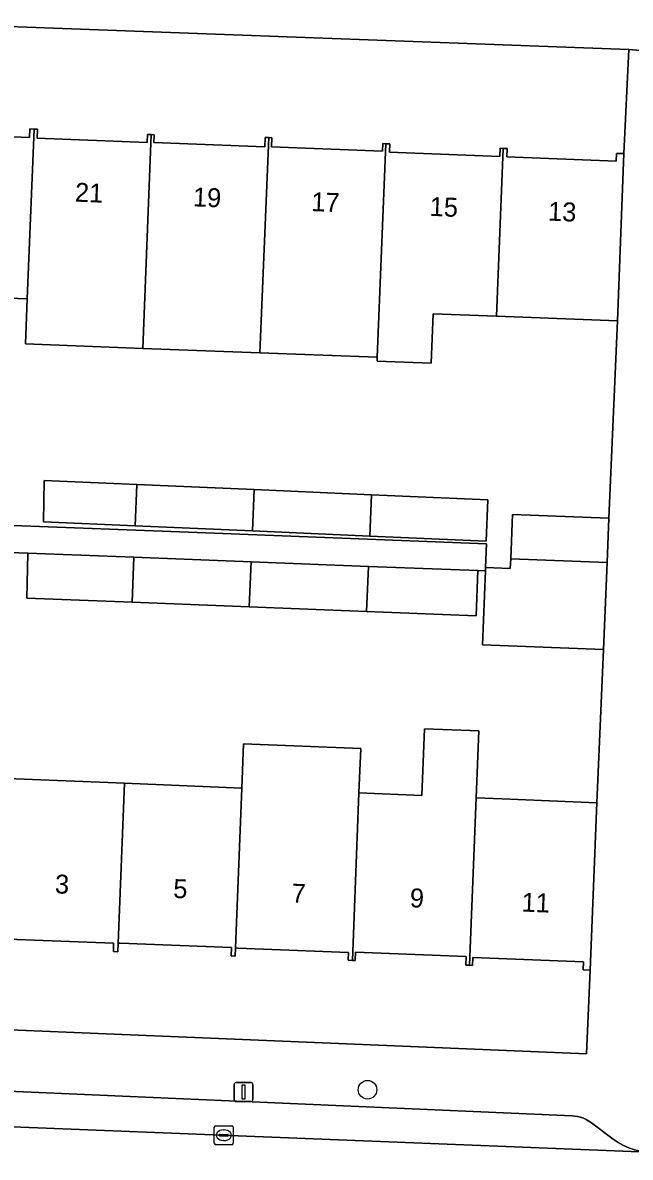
# Model space of a CAD drawing. Extents: x 161354 to 162026, y 386504 to 387460.
# Drawn here: x 161814.8 to 161846.8, y 386692 to 386751.9 of the extents above; entities that cross this region are included whole.
import ezdxf

# ---------------------------------------------------------------- set-up
doc = ezdxf.new("R2010")
doc.units = 0
for name, color, linetype in [('IMGEO_Boom', 7, 'Continuous'), ('IMGEO_Erf', 7, 'Continuous'), ('IMGEO_Kolk', 7, 'Continuous'), ('IMGEO_Lichtmast', 7, 'Continuous'), ('IMGEO_Muur', 7, 'Continuous'), ('IMGEO_Pand', 7, 'Continuous'), ('IMGEO_Pand_nummerreeks', 7, 'Continuous'), ('IMGEO_Parkeervlak_open', 7, 'Continuous'), ('IMGEO_Rijbaan_lokaal_open', 7, 'Continuous'), ('IMGEO_Voetpad_gesloten', 7, 'Continuous'), ('IMGEO_Voetpad_open', 7, 'Continuous')]:
    doc.layers.add(name, color=color, linetype=linetype)

msp = doc.modelspace()

# ---------------------------------------------------------------- linework, layer by layer
at = {"layer": 'IMGEO_Boom'}
msp.add_circle((161832.96, 386695.526), 0.489, dxfattribs=at)
at = {"layer": 'IMGEO_Erf'}
for points in [[(161809.293, 386746.023), (161815.126, 386745.793), (161815.144, 386746.245), (161815.365, 386746.236), (161815.544, 386746.229), (161815.525, 386745.761), (161821.329, 386745.532), (161821.346, 386745.956), (161821.552, 386745.948), (161821.705, 386745.942), (161821.689, 386745.529), (161827.535, 386745.298), (161827.555, 386745.795), (161827.744, 386745.787), (161827.919, 386745.78), (161827.9, 386745.297), (161833.748, 386745.067), (161833.764, 386745.473), (161833.929, 386745.466), (161834.13, 386745.458), (161834.112, 386745.015), (161839.945, 386744.785), (161839.962, 386745.225), (161840.117, 386745.219), (161840.331, 386745.21), (161840.314, 386744.776), (161846.077, 386744.549), (161846.094, 386744.958), (161846.478, 386744.946), (161846.74, 386750.435), (161809.266, 386751.829)], [(161814.265, 386725.315), (161823.973, 386724.938), (161839.242, 386724.345), (161839.186, 386723.088), (161840.493, 386723.035), (161840.513, 386723.552), (161840.606, 386725.894), (161845.692, 386725.694), (161846.151, 386736.123), (161841.155, 386736.308), (161839.762, 386736.36), (161836.431, 386736.483), (161836.322, 386733.886), (161833.463, 386733.992), (161833.472, 386734.206), (161827.282, 386734.435), (161821.099, 386734.664), (161814.906, 386734.894), (161815.005, 386737.277), (161808.728, 386737.51)], [(161813.957, 386711.965), (161820.14, 386711.709), (161826.323, 386711.453), (161826.421, 386713.789), (161832.609, 386713.533), (161832.506, 386711.197), (161835.832, 386711.059), (161835.97, 386714.581), (161838.826, 386714.469), (161838.688, 386710.94), (161840.072, 386710.883), (161845.067, 386710.676), (161845.419, 386718.76), (161839.025, 386719.013), (161839.179, 386722.914), (161838.778, 386722.93), (161838.686, 386720.551), (161832.908, 386720.776), (161826.723, 386721.017), (161820.537, 386721.258), (161814.983, 386721.474), (161815.032, 386723.854), (161813.139, 386723.923)], [(161844.701, 386701.843), (161844.343, 386701.857), (161844.359, 386702.284), (161838.517, 386702.509), (161838.501, 386702.091), (161838.342, 386702.097), (161838.15, 386702.105), (161838.168, 386702.565), (161832.327, 386702.791), (161832.31, 386702.343), (161832.16, 386702.349), (161831.934, 386702.358), (161831.95, 386702.779), (161826.123, 386703.004), (161825.994, 386703.009), (161825.977, 386702.586), (161825.766, 386702.594), (161825.783, 386703.041), (161819.911, 386703.267), (161819.81, 386703.271), (161819.792, 386702.808), (161819.548, 386702.817), (161819.565, 386703.268), (161814.006, 386703.483)], [(161798.896, 386699.324), (161844.507, 386697.427), (161844.701, 386701.843)]]:
    msp.add_lwpolyline(points, dxfattribs=at)
msp.add_lwpolyline([(161826.982, 386727.208), (161833.167, 386726.938), (161839.315, 386726.669), (161839.22, 386724.486), (161833.075, 386724.754), (161826.891, 386725.024), (161820.705, 386725.294), (161815.857, 386725.506), (161815.906, 386727.691), (161820.796, 386727.478)], close=True, dxfattribs=at)
at = {"layer": 'IMGEO_Kolk'}
for p, q in [((161824.95, 386693.625), (161825.802, 386693.625)), ((161824.875, 386692.699), (161824.875, 386693.551)), ((161825.134, 386693.119), (161825.134, 386693.131)), ((161825.572, 386693.082), (161825.174, 386693.082)), ((161825.177, 386693.168), (161825.575, 386693.168)), ((161825.363, 386693.405), (161825.388, 386693.405)), ((161825.618, 386693.131), (161825.618, 386693.119)), ((161825.876, 386693.551), (161825.876, 386692.699)), ((161825.802, 386692.625), (161824.95, 386692.625)), ((161825.386, 386692.845), (161825.361, 386692.845))]:
    msp.add_line(p, q, dxfattribs=at)
for points in [[(161824.95, 386693.625), (161825.802, 386693.625)], [(161824.875, 386692.699), (161824.875, 386693.551)], [(161825.876, 386693.551), (161825.876, 386692.699)], [(161825.802, 386692.625), (161824.95, 386692.625)]]:
    msp.add_lwpolyline(points, dxfattribs=at)
for centre, radius, start, end in [((161824.952, 386693.549), 0.0765, 91.55205, 178.44795), ((161824.952, 386693.549), 0.0765, 91.55205, 178.44795), ((161825.8, 386693.549), 0.0765, 1.55205, 88.44795), ((161825.8, 386693.549), 0.0765, 1.55205, 88.44795), ((161825.174, 386693.128), 0.0403, 85.87752, 175.75265), ((161825.171, 386693.118), 0.0366, 178.93798, 274.71019), ((161825.575, 386693.125), 0.043, 264.86636, 352.45326), ((161825.579, 386693.13), 0.0386, 1.73085, 96.63898), ((161824.952, 386692.701), 0.0765, 181.55205, 268.44795), ((161824.952, 386692.701), 0.0765, 181.55205, 268.44795), ((161825.8, 386692.701), 0.0765, 271.55205, 358.44795), ((161825.8, 386692.701), 0.0765, 271.55205, 358.44795)]:
    msp.add_arc(centre, radius, start, end, dxfattribs=at)
for centre, major_axis, ratio, start_param, end_param in [((161825.362, 386693.125), (-0.387, 0.002), 0.722429, 4.712389, 7.853982), ((161825.387, 386693.125), (-0.39, 0.002), 0.717154, 1.570796, 4.712389)]:
    msp.add_ellipse(centre, major_axis=major_axis, ratio=ratio, start_param=start_param, end_param=end_param, dxfattribs=at)
at = {"layer": 'IMGEO_Lichtmast'}
for p, q in [((161825.923, 386695.006), (161825.923, 386695.806)), ((161825.923, 386695.806), (161825.923, 386695.006)), ((161826.023, 386695.906), (161826.813, 386695.906)), ((161826.813, 386695.906), (161826.023, 386695.906)), ((161826.913, 386695.806), (161826.913, 386695.006)), ((161826.913, 386695.006), (161826.913, 386695.806)), ((161826.813, 386694.906), (161826.023, 386694.906)), ((161826.023, 386694.906), (161826.813, 386694.906))]:
    msp.add_line(p, q, dxfattribs=at)
msp.add_lwpolyline([(161826.343, 386695.781), (161826.493, 386695.781), (161826.493, 386695.031), (161826.343, 386695.031), (161826.343, 386695.781)], dxfattribs=at)
for centre, start, end in [((161826.023, 386695.806), 90, 180), ((161826.023, 386695.806), 90, 180), ((161826.813, 386695.806), 0, 90), ((161826.813, 386695.806), 360, 90), ((161826.023, 386695.006), 180, 270), ((161826.023, 386695.006), 180, 270), ((161826.813, 386695.006), 270, 0), ((161826.813, 386695.006), 270, 0)]:
    msp.add_arc(centre, 0.1, start, end, dxfattribs=at)
at = {"layer": 'IMGEO_Muur'}
msp.add_lwpolyline([(161845.419, 386718.76), (161845.067, 386710.676)], dxfattribs=at)
at = {"layer": 'IMGEO_Pand'}
for points in [[(161808.827, 386740.749), (161808.735, 386737.728), (161808.728, 386737.51), (161815.005, 386737.277), (161815.365, 386746.236), (161815.144, 386746.245), (161815.126, 386745.793), (161809.293, 386746.023), (161809.311, 386746.486), (161808.997, 386746.481)], [(161821.552, 386745.948), (161821.346, 386745.956), (161821.329, 386745.532), (161815.525, 386745.761), (161815.544, 386746.229), (161815.365, 386746.236), (161815.005, 386737.277), (161814.906, 386734.894), (161821.099, 386734.664)], [(161827.282, 386734.435), (161827.744, 386745.787), (161827.555, 386745.795), (161827.535, 386745.298), (161821.689, 386745.529), (161821.705, 386745.942), (161821.552, 386745.948), (161821.099, 386734.664)], [(161833.472, 386734.206), (161833.929, 386745.466), (161833.764, 386745.473), (161833.748, 386745.067), (161827.9, 386745.297), (161827.919, 386745.78), (161827.744, 386745.787), (161827.282, 386734.435)], [(161833.463, 386733.992), (161836.322, 386733.886), (161836.431, 386736.483), (161839.762, 386736.36), (161840.117, 386745.219), (161839.962, 386745.225), (161839.945, 386744.785), (161834.112, 386745.015), (161834.13, 386745.458), (161833.929, 386745.466), (161833.472, 386734.206)], [(161846.478, 386744.946), (161846.094, 386744.958), (161846.077, 386744.549), (161840.314, 386744.776), (161840.331, 386745.21), (161840.117, 386745.219), (161839.762, 386736.36), (161841.155, 386736.308), (161846.151, 386736.123)], [(161815.906, 386727.691), (161815.857, 386725.506), (161820.705, 386725.294), (161820.796, 386727.478)], [(161820.796, 386727.478), (161820.705, 386725.294), (161826.891, 386725.024), (161826.982, 386727.208)], [(161826.982, 386727.208), (161826.891, 386725.024), (161833.075, 386724.754), (161833.167, 386726.938)], [(161839.22, 386724.486), (161839.315, 386726.669), (161833.167, 386726.938), (161833.075, 386724.754)], [(161845.692, 386725.694), (161840.606, 386725.894), (161840.513, 386723.552), (161845.6, 386723.354)], [(161815.032, 386723.854), (161814.983, 386721.474), (161820.537, 386721.258), (161820.636, 386723.636)], [(161820.636, 386723.636), (161820.537, 386721.258), (161826.723, 386721.017), (161826.823, 386723.395)], [(161845.6, 386723.354), (161840.513, 386723.552), (161840.493, 386723.035), (161839.186, 386723.088), (161839.179, 386722.914), (161839.025, 386719.013), (161845.419, 386718.76)], [(161826.823, 386723.395), (161826.723, 386721.017), (161832.908, 386720.776), (161833.008, 386723.154)], [(161838.686, 386720.551), (161838.778, 386722.93), (161833.008, 386723.154), (161832.908, 386720.776)], [(161838.688, 386710.94), (161838.826, 386714.469), (161835.97, 386714.581), (161835.832, 386711.059), (161832.506, 386711.197), (161832.16, 386702.349), (161832.31, 386702.343), (161832.327, 386702.791), (161838.168, 386702.565), (161838.15, 386702.105), (161838.342, 386702.097)], [(161832.506, 386711.197), (161832.609, 386713.533), (161826.421, 386713.789), (161826.323, 386711.453), (161825.994, 386703.009), (161826.123, 386703.004), (161831.95, 386702.779), (161831.934, 386702.358), (161832.16, 386702.349)], [(161820.14, 386711.709), (161813.957, 386711.965), (161813.626, 386703.497), (161814.006, 386703.483), (161819.565, 386703.268), (161819.548, 386702.817), (161819.792, 386702.808), (161819.81, 386703.271)], [(161826.323, 386711.453), (161820.14, 386711.709), (161819.81, 386703.271), (161819.911, 386703.267), (161825.783, 386703.041), (161825.766, 386702.594), (161825.977, 386702.586), (161825.994, 386703.009)], [(161845.067, 386710.676), (161840.072, 386710.883), (161838.688, 386710.94), (161838.342, 386702.097), (161838.501, 386702.091), (161838.517, 386702.509), (161844.359, 386702.284), (161844.343, 386701.857), (161844.701, 386701.843)]]:
    msp.add_lwpolyline(points, close=True, dxfattribs=at)
at = {"layer": 'IMGEO_Parkeervlak_open'}
msp.add_lwpolyline([(161800.538, 386694.114), (161847.757, 386692.233), (161847.673, 386692.241), (161847.36, 386692.287), (161847.054, 386692.361), (161846.755, 386692.462), (161846.466, 386692.59), (161846.189, 386692.742), (161845.928, 386692.919), (161844.77, 386693.784), (161844.636, 386693.875), (161844.495, 386693.953), (161844.347, 386694.018), (161844.195, 386694.07), (161844.038, 386694.108), (161843.878, 386694.132), (161843.765, 386694.14), (161803.54, 386695.916)], dxfattribs=at)
at = {"layer": 'IMGEO_Rijbaan_lokaal_open'}
msp.add_lwpolyline([(161847.757, 386692.233), (161800.538, 386694.114), (161800.294, 386694.048)], dxfattribs=at)
at = {"layer": 'IMGEO_Voetpad_gesloten'}
msp.add_lwpolyline([(161808.129, 386725.704), (161802.042, 386725.94), (161801.983, 386724.476), (161808.189, 386724.232), (161813.143, 386724.038), (161813.139, 386723.923), (161815.032, 386723.854), (161820.636, 386723.636), (161826.823, 386723.395), (161833.008, 386723.154), (161838.778, 386722.93), (161839.179, 386722.914), (161839.186, 386723.088), (161839.242, 386724.345), (161823.973, 386724.938), (161814.265, 386725.315), (161808.123, 386725.553)], close=True, dxfattribs=at)
at = {"layer": 'IMGEO_Voetpad_open'}
for points in [[(161809.386, 386754.894), (161809.266, 386751.829), (161846.74, 386750.435), (161852.462, 386749.947), (161857.068, 386749.79), (161862.119, 386749.599), (161865.337, 386749.508), (161865.363, 386750.354), (161865.845, 386750.335), (161865.974, 386750.326), (161866.182, 386750.297), (161866.387, 386750.249), (161866.586, 386750.184), (161866.779, 386750.1), (161866.964, 386750), (161867.13, 386749.89), (161867.294, 386749.759), (161870.152, 386749.67), (161872.918, 386749.566), (161913.776, 386748.036)], [(161852.462, 386749.947), (161846.74, 386750.435), (161846.478, 386744.946), (161846.151, 386736.123), (161845.692, 386725.694), (161845.6, 386723.354), (161845.419, 386718.76), (161845.067, 386710.676), (161844.701, 386701.843), (161844.507, 386697.427), (161798.896, 386699.324)], [(161803.54, 386695.916), (161843.765, 386694.14), (161843.878, 386694.132), (161844.038, 386694.108), (161844.195, 386694.07), (161844.347, 386694.018), (161844.495, 386693.953), (161844.636, 386693.875), (161844.77, 386693.784), (161845.928, 386692.919), (161846.189, 386692.742), (161846.466, 386692.59), (161846.755, 386692.462), (161847.054, 386692.361), (161847.36, 386692.287), (161847.673, 386692.241), (161847.757, 386692.233), (161847.883, 386692.226), (161854.618, 386691.959), (161854.635, 386692.459), (161854.654, 386694.502), (161854.98, 386700.421)]]:
    msp.add_lwpolyline(points, dxfattribs=at)

# ---------------------------------------------------------------- texts
at = {"layer": 'IMGEO_Pand_nummerreeks'}
for s, rotation, p in [('21', 357.70599, (161817.509, 386742.411)), ('19', 357.70599, (161823.734, 386742.162)), ('17', 357.70599, (161829.98, 386741.912)), ('15', 357.70599, (161836.227, 386741.661)), ('13', 357.70599, (161842.473, 386741.411)), ('3', 357.76546, (161816.454, 386705.894)), ('5', 357.76546, (161822.695, 386705.651)), ('7', 357.76546, (161828.937, 386705.407)), ('9', 357.76546, (161835.179, 386705.163)), ('11', 357.76495, (161841.076, 386704.934))]:
    msp.add_text(s, height=1, rotation=rotation, dxfattribs=at).set_placement(p)

doc.saveas('drawing.dxf')
